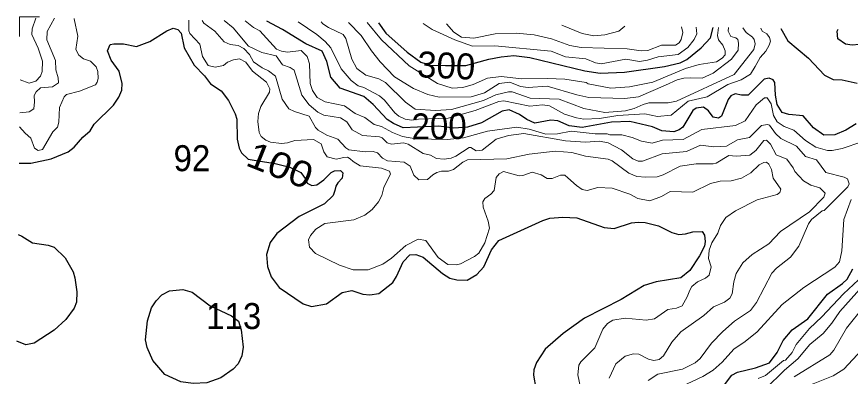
# Model space of a CAD drawing. Extents: x 673.6 to 698.9, y 7012 to 7040.1.
# Drawn here: x 674.012 to 676.578, y 7038.944 to 7040.051 of the extents above; entities that cross this region are included whole.
import ezdxf
from ezdxf.enums import TextEntityAlignment as Align

# ---------------------------------------------------------------- set-up
doc = ezdxf.new("R2010")
doc.units = 0
doc.header["$LTSCALE"] = 0.032
for name, color, linetype, lineweight in [('1', 7, 'Continuous', 25), ('2', 7, 'Continuous', 13), ('63', 7, 'Continuous', 13)]:
    doc.layers.add(name, color=color, linetype=linetype, lineweight=lineweight)
doc.layers.add('21', color=7, linetype='Continuous')
doc.layers.add('61', color=7, linetype='Continuous')

msp = doc.modelspace()

# ---------------------------------------------------------------- linework, layer by layer
at = {"layer": '1'}
for points in [[(676.5955, 7039.7209), (676.564, 7039.7015), (676.5306, 7039.6868), (676.4966, 7039.6866), (676.4646, 7039.7091), (676.4331, 7039.7461), (676.3883, 7039.7496), (676.3687, 7039.7559), (676.3527, 7039.7803), (676.3476, 7039.8095), (676.3457, 7039.8483), (676.3405, 7039.8566), (676.328, 7039.8616), (676.3123, 7039.8586), (676.2635, 7039.8091), (676.2435, 7039.8088), (676.2233, 7039.8131), (676.2097, 7039.8075), (676.2016, 7039.7956), (676.1815, 7039.7442), (676.1719, 7039.7381), (676.1563, 7039.7415), (676.1417, 7039.7608), (676.1265, 7039.7724), (676.1039, 7039.7691), (676.0937, 7039.7619), (676.0621, 7039.7103), (676.0511, 7039.7023), (676.0349, 7039.6963), (675.9982, 7039.6995), (675.9692, 7039.7121), (675.8992, 7039.7282), (675.8433, 7039.7259), (675.7527, 7039.7102), (675.7125, 7039.7152), (675.6773, 7039.73), (675.6565, 7039.7324), (675.6067, 7039.7235), (675.5825, 7039.7345), (675.5593, 7039.7502), (675.5275, 7039.7638), (675.506, 7039.7596), (675.4428, 7039.7238), (675.3992, 7039.7104), (675.3575, 7039.7082), (675.3119, 7039.7136), (675.2459, 7039.7104), (675.2018, 7039.7085), (675.1714, 7039.7218), (675.152, 7039.7347), (675.1091, 7039.7801), (675.0803, 7039.8048), (675.0073, 7039.8312), (674.9792, 7039.8644), (674.9669, 7039.9133), (674.952, 7039.9444), (674.9016, 7039.9674), (674.8305, 7040.011), (674.7819, 7040.0369)], [(675.1257, 7040.0321), (675.1487, 7039.9997), (675.214, 7039.9415), (675.2565, 7039.9106), (675.2858, 7039.9016), (675.3324, 7039.9006), (675.395, 7039.9009), (675.4652, 7039.9197), (675.5036, 7039.9275), (675.5426, 7039.9314), (675.5911, 7039.9257), (675.7605, 7039.8838), (675.8075, 7039.8772), (675.8828, 7039.8805), (676.0058, 7039.8979), (676.0542, 7039.9088), (676.0752, 7039.9189), (676.1185, 7039.9547), (676.1473, 7039.9859), (676.1559, 7040.0179)], [(674.0195, 7039.5999), (674.0552, 7039.5995), (674.1177, 7039.6135), (674.1701, 7039.6349), (674.189, 7039.649), (674.2161, 7039.6801), (674.2382, 7039.6992), (674.2507, 7039.7197), (674.3096, 7039.7781), (674.3264, 7039.8033), (674.3358, 7039.8243), (674.3366, 7039.8447), (674.3273, 7039.8834), (674.3028, 7039.917), (674.2915, 7039.9462), (674.2995, 7039.9648), (674.3112, 7039.9675), (674.341, 7039.9668), (674.3813, 7039.9595), (674.4217, 7039.9747), (674.4739, 7040.0078), (674.494, 7040.0159), (674.5084, 7040.0118), (674.5179, 7040), (674.5277, 7039.9552), (674.5583, 7039.9012), (674.5897, 7039.8689), (674.6089, 7039.844), (674.641, 7039.8227), (674.6643, 7039.7928), (674.6844, 7039.7521), (674.6892, 7039.7358), (674.691, 7039.6736), (674.6972, 7039.6463), (674.7044, 7039.6319), (674.7242, 7039.6122), (674.749, 7039.6086), (674.808, 7039.5994), (674.8532, 7039.5873), (674.8867, 7039.5711), (674.9026, 7039.5483), (674.9058, 7039.5384), (674.9205, 7039.5313), (674.9355, 7039.5332), (674.9576, 7039.5491), (674.9803, 7039.5716), (674.9904, 7039.5761), (675.0084, 7039.5779), (675.016, 7039.5701), (675.0143, 7039.5539), (675.0007, 7039.5398), (674.9944, 7039.5293), (674.9916, 7039.516), (674.9858, 7039.5), (674.9591, 7039.4745), (674.8815, 7039.4358), (674.8128, 7039.3836), (674.7919, 7039.3557), (674.781, 7039.319), (674.7838, 7039.2818), (674.7951, 7039.2497), (674.8197, 7039.2176), (674.8935, 7039.1674), (674.9193, 7039.159), (674.9656, 7039.1675), (675.0135, 7039.2023), (675.0439, 7039.2082), (675.0775, 7039.1967), (675.0988, 7039.1952), (675.1271, 7039.1987), (675.1696, 7039.2327), (675.1811, 7039.251), (675.2019, 7039.2967), (675.2222, 7039.3183), (675.241, 7039.3191), (675.2628, 7039.3109), (675.3231, 7039.2606), (675.3451, 7039.2461), (675.3667, 7039.2411), (675.3983, 7039.2398), (675.4279, 7039.2568), (675.4501, 7039.2812), (675.4739, 7039.3328), (675.4962, 7039.3618), (675.6314, 7039.4234), (675.6527, 7039.4302), (675.6933, 7039.4342), (675.7357, 7039.4318), (675.8199, 7039.4022), (675.8507, 7039.3989), (675.9042, 7039.4162), (675.9251, 7039.4186), (675.9465, 7039.4169), (675.9876, 7039.4071), (676.0284, 7039.3867)], [(676.3638, 7040.015), (676.3857, 7039.977), (676.4497, 7039.9229), (676.4985, 7039.8709), (676.5254, 7039.8574), (676.5533, 7039.8566), (676.5992, 7039.846)], [(676.6361, 7040.0112), (676.6364, 7040.0019), (676.623, 7039.9826), (676.6055, 7039.9653), (676.5835, 7039.9627), (676.5629, 7039.966), (676.5391, 7039.9825), (676.538, 7040.0059), (676.5404, 7040.0125)], [(676.0284, 7039.3867), (676.0497, 7039.3801), (676.0711, 7039.3824), (676.0929, 7039.389), (676.1216, 7039.3898), (676.1289, 7039.378)], [(674.0165, 7039.3802), (674.0274, 7039.3756), (674.061, 7039.3552), (674.1094, 7039.3478), (674.1271, 7039.3413), (674.1616, 7039.3084), (674.1855, 7039.2658), (674.1914, 7039.2469), (674.197, 7039.2037), (674.1961, 7039.1725), (674.1894, 7039.1537), (674.1631, 7039.1183), (674.1279, 7039.0855), (674.0655, 7039.0464), (674.04, 7039.0408), (674.012, 7039.0521)], [(676.1289, 7039.378), (676.1309, 7039.3593), (676.1289, 7039.3448), (676.1135, 7039.315), (676.0837, 7039.2699), (676.0558, 7039.2475), (675.9802, 7039.2344), (675.9436, 7039.2232), (675.8729, 7039.1805), (675.7599, 7039.1224), (675.694, 7039.0757), (675.639, 7039.0272), (675.6119, 7038.9867), (675.6039, 7038.9634), (675.6031, 7038.9478), (675.6096, 7038.9062)], [(676.1691, 7038.8886), (676.2131, 7038.9479), (676.2312, 7038.9569), (676.2864, 7038.9698), (676.3294, 7038.9857), (676.3528, 7039.0168), (676.3709, 7039.0546), (676.3994, 7039.0874), (676.4467, 7039.1209), (676.5081, 7039.197), (676.5534, 7039.2294), (676.5678, 7039.2431), (676.5859, 7039.2744)]]:
    msp.add_lwpolyline(points, dxfattribs=at)
msp.add_lwpolyline([(674.6943, 7039.1135), (674.7032, 7039.0867), (674.7093, 7039.0333), (674.7054, 7039.0071), (674.6933, 7038.9821), (674.6787, 7038.9662), (674.6399, 7038.9392), (674.5972, 7038.924), (674.5552, 7038.9223), (674.5176, 7038.9267), (674.4676, 7038.9493), (674.4308, 7038.9927), (674.4141, 7039.0321), (674.4082, 7039.0558), (674.4147, 7039.1142), (674.4267, 7039.1548), (674.4417, 7039.1767), (674.4584, 7039.1943), (674.4825, 7039.2067), (674.5232, 7039.2107), (674.5518, 7039.203), (674.6074, 7039.1611), (674.6735, 7039.1299)], close=True, dxfattribs=at)
at = {"layer": '2'}
for points in [[(674.1887, 7040.0451), (674.1888, 7040.0446), (674.2002, 7039.9909), (674.1939, 7039.9496), (674.203, 7039.9322), (674.2176, 7039.9208), (674.2389, 7039.9141), (674.257, 7039.8966), (674.2619, 7039.8818), (674.2627, 7039.8607), (674.26, 7039.849), (674.2544, 7039.8411), (674.2053, 7039.8221), (674.165, 7039.8114), (674.1578, 7039.8043), (674.1437, 7039.7711), (674.1419, 7039.7259), (674.138, 7039.7111), (674.1231, 7039.6963), (674.092, 7039.6417), (674.0778, 7039.6389), (674.0668, 7039.6459), (674.0559, 7039.6769), (674.0377, 7039.6922), (674.0211, 7039.712)], [(674.0217, 7039.7553), (674.0504, 7039.7578), (674.0647, 7039.7668), (674.0672, 7039.7883), (674.0656, 7039.8086), (674.0725, 7039.8199), (674.0857, 7039.8323), (674.1218, 7039.8353), (674.1403, 7039.8474), (674.1402, 7039.863), (674.1328, 7039.8874), (674.1316, 7039.9165), (674.1053, 7039.9795), (674.1058, 7040.005), (674.1281, 7040.0459)], [(674.0713, 7040.0467), (674.06, 7040.013), (674.0582, 7039.9964), (674.0777, 7039.9538), (674.0912, 7039.9143), (674.09, 7039.8818), (674.085, 7039.8679), (674.0712, 7039.8519), (674.0502, 7039.846), (674.0231, 7039.8564)], [(674.5423, 7040.0402), (674.5416, 7040.0069), (674.5449, 7039.9995), (674.5754, 7039.9665), (674.5837, 7039.9285), (674.6018, 7039.901), (674.6234, 7039.8954), (674.6487, 7039.901), (674.6611, 7039.9111), (674.6791, 7039.9184), (674.6979, 7039.9215), (674.7178, 7039.9107), (674.7377, 7039.8829), (674.7811, 7039.8498), (674.7908, 7039.8285), (674.7903, 7039.8188), (674.7639, 7039.7749), (674.7567, 7039.7526), (674.7541, 7039.7284), (674.7583, 7039.6943), (674.7643, 7039.6822), (674.7786, 7039.6704), (674.793, 7039.6644), (674.8269, 7039.6603), (674.8459, 7039.6624), (674.8683, 7039.67), (674.9254, 7039.6733), (674.9495, 7039.6595), (674.9573, 7039.6352), (674.9674, 7039.6199), (674.9949, 7039.6127), (675.0185, 7039.6174), (675.03, 7039.6184), (675.0384, 7039.6132), (675.0478, 7039.6049), (675.0688, 7039.5915), (675.1354, 7039.5845), (675.1591, 7039.5754), (675.1629, 7039.5657), (675.1568, 7039.5545), (675.1417, 7039.525), (675.1361, 7039.5005), (675.1257, 7039.4814), (675.106, 7039.4575), (675.0836, 7039.4401), (675.0497, 7039.4252), (674.961, 7039.4145), (674.9327, 7039.3967), (674.916, 7039.377), (674.9104, 7039.3644), (674.9137, 7039.3412), (674.9323, 7039.3222), (675.0052, 7039.2859), (675.048, 7039.2719), (675.0943, 7039.2716), (675.1392, 7039.2887), (675.1661, 7039.3079), (675.2096, 7039.3467), (675.2483, 7039.366), (675.2712, 7039.3617), (675.3098, 7039.3099), (675.3391, 7039.2879), (675.3645, 7039.2875), (675.3784, 7039.2904), (675.4211, 7039.3125), (675.4344, 7039.3233), (675.4528, 7039.3549), (675.4672, 7039.3999), (675.4637, 7039.4214), (675.4533, 7039.4497), (675.448, 7039.4644), (675.4471, 7039.4805), (675.4533, 7039.4916), (675.471, 7039.5045), (675.482, 7039.5163), (675.4879, 7039.5555), (675.4967, 7039.5668), (675.5105, 7039.5747), (675.5586, 7039.5608), (675.5704, 7039.5616), (675.5987, 7039.5721), (675.6269, 7039.5643), (675.645, 7039.5524), (675.6607, 7039.5524), (675.6858, 7039.5629), (675.6988, 7039.5632), (675.7089, 7039.5545), (675.7349, 7039.531), (675.7525, 7039.5194), (675.7677, 7039.5157), (675.8009, 7039.5247), (675.8446, 7039.5229), (675.8998, 7039.5044), (675.9243, 7039.4915), (675.961, 7039.4844)], [(674.6503, 7039.9737), (674.6221, 7040.0068), (674.5883, 7040.0314), (674.5831, 7040.0396)], [(674.651, 7040.0387), (674.6783, 7040.0163), (674.7251, 7039.9605), (674.7671, 7039.941), (674.8103, 7039.9307), (674.8303, 7039.903), (674.8536, 7039.8944), (674.8664, 7039.8862), (674.8902, 7039.8092), (674.9122, 7039.7799), (674.9387, 7039.7574), (674.9578, 7039.7482), (675.0085, 7039.7398), (675.0278, 7039.7276), (675.0451, 7039.7022), (675.0764, 7039.6851), (675.129, 7039.6806), (675.1367, 7039.6775), (675.1523, 7039.6629), (675.1655, 7039.6587), (675.203, 7039.6628), (675.2167, 7039.6585), (675.2634, 7039.6295), (675.2853, 7039.6249), (675.3039, 7039.6143), (675.3281, 7039.6126), (675.3495, 7039.6154), (675.3642, 7039.6216), (675.4045, 7039.6478), (675.4096, 7039.6477), (675.4265, 7039.6379), (675.4451, 7039.6398), (675.4875, 7039.6734), (675.5261, 7039.6849), (675.5732, 7039.6915), (675.701, 7039.6685), (675.7633, 7039.6651), (675.8055, 7039.6676), (675.8331, 7039.6626), (675.8736, 7039.6408), (675.9081, 7039.6129), (675.9248, 7039.6061), (675.9379, 7039.6063), (675.9985, 7039.6284), (676.0741, 7039.6354), (676.1166, 7039.6552), (676.1574, 7039.6504), (676.1965, 7039.6518), (676.2306, 7039.6723), (676.2677, 7039.6785), (676.3048, 7039.7159), (676.3228, 7039.7192), (676.3296, 7039.7165), (676.3476, 7039.6915), (676.3639, 7039.6755), (676.4123, 7039.6527), (676.4397, 7039.6209), (676.474, 7039.6101), (676.5031, 7039.5714), (676.5595, 7039.5574), (676.5695, 7039.5513), (676.5742, 7039.5361), (676.5702, 7039.5271), (676.4976, 7039.4548), (676.4913, 7039.4537), (676.4589, 7039.4271), (676.4493, 7039.4134), (676.4194, 7039.344), (676.3936, 7039.3102), (676.3505, 7039.2769), (676.3362, 7039.2614), (676.2896, 7039.1715), (676.2706, 7039.1469), (676.2212, 7039.1133), (676.1854, 7039.0823), (676.1511, 7039.0455), (676.1154, 7038.9985), (676.1007, 7038.9852), (676.061, 7038.9661), (675.9852, 7038.9507), (675.9553, 7038.931)], [(676.6134, 7039.6652), (676.5526, 7039.6454), (676.5217, 7039.6389), (676.5073, 7039.6389), (676.4723, 7039.6496), (676.4402, 7039.67), (676.4045, 7039.7019), (676.3744, 7039.7124), (676.3524, 7039.7275), (676.3411, 7039.747), (676.3339, 7039.7829), (676.3224, 7039.8015), (676.3137, 7039.8013), (676.2884, 7039.7794), (676.2543, 7039.7298), (676.2249, 7039.7164), (676.1208, 7039.7037), (676.0637, 7039.6726), (675.9994, 7039.6708), (675.9683, 7039.6619), (675.9353, 7039.6676), (675.9064, 7039.6793), (675.8742, 7039.6873), (675.8374, 7039.6874), (675.8294, 7039.6906), (675.7925, 7039.6907), (675.719, 7039.6986), (675.6768, 7039.6907), (675.6411, 7039.689), (675.5895, 7039.7047), (675.5511, 7039.7103), (675.4617, 7039.6988), (675.3874, 7039.6783), (675.3372, 7039.6731), (675.2405, 7039.6752), (675.1995, 7039.6817), (675.1688, 7039.6941), (675.1353, 7039.7127), (675.112, 7039.7191), (675.0838, 7039.7409), (675.0535, 7039.7526), (675.0213, 7039.7768), (674.9611, 7039.789), (674.9368, 7039.8025), (674.9227, 7039.8241), (674.9153, 7039.8447), (674.9134, 7039.9053), (674.9066, 7039.9287), (674.8873, 7039.9471), (674.8459, 7039.9421), (674.827, 7039.9446), (674.8113, 7039.9511), (674.7601, 7040.0076), (674.7412, 7040.0179), (674.7148, 7040.0378)], [(674.8789, 7040.0355), (674.936, 7039.9961), (674.9615, 7039.9747), (674.9786, 7039.9549), (675.0111, 7039.8902), (675.0416, 7039.8544), (675.0633, 7039.8382), (675.0807, 7039.8327), (675.1286, 7039.8077), (675.1444, 7039.7941), (675.1763, 7039.755), (675.1887, 7039.7445), (675.2083, 7039.7351), (675.228, 7039.7326), (675.2486, 7039.7358), (675.3399, 7039.7387), (675.4237, 7039.7626), (675.4965, 7039.7893), (675.5119, 7039.7917), (675.5915, 7039.7753), (675.6301, 7039.7793), (675.652, 7039.7769), (675.6986, 7039.7505), (675.7349, 7039.7391), (675.758, 7039.7359), (675.8062, 7039.7375), (675.8622, 7039.7466), (675.9454, 7039.7523), (675.9843, 7039.7441), (676.0263, 7039.7479), (676.079, 7039.7913), (676.1378, 7039.8043), (676.2006, 7039.8423), (676.2422, 7039.857), (676.2703, 7039.8739), (676.2848, 7039.8979), (676.3001, 7039.9254), (676.3181, 7039.9452), (676.3287, 7039.9633), (676.3323, 7039.9757), (676.3292, 7039.9863), (676.3208, 7039.9977), (676.3069, 7040.006), (676.3021, 7040.0158)], [(676.2467, 7040.0166), (676.2577, 7040.0023), (676.2774, 7039.9881), (676.2817, 7039.9809), (676.2851, 7039.9673), (676.2815, 7039.9498), (676.2203, 7039.8729), (676.0433, 7039.7909), (676.0175, 7039.786), (675.9582, 7039.786), (675.9404, 7039.7808), (675.913, 7039.7685), (675.8862, 7039.761), (675.8221, 7039.7556), (675.7582, 7039.7685), (675.6822, 7039.7973), (675.5926, 7039.7998), (675.5372, 7039.8192), (675.5254, 7039.8196), (675.487, 7039.8099), (675.449, 7039.7929), (675.3499, 7039.7655), (675.3011, 7039.7622), (675.2384, 7039.7667), (675.2088, 7039.7882), (675.1477, 7039.8483), (675.1272, 7039.8598), (675.0866, 7039.8708), (675.0592, 7039.8914), (675.0436, 7039.9196), (675.0253, 7039.9841), (675.0166, 7039.9958), (674.9718, 7040.0175), (674.9546, 7040.0291), (674.949, 7040.0346)], [(675.0333, 7040.0334), (675.0728, 7039.9934), (675.1039, 7039.9456), (675.1305, 7039.9117), (675.1751, 7039.8662), (675.2332, 7039.8295), (675.278, 7039.8109), (675.3124, 7039.8033), (675.4112, 7039.8042), (675.4518, 7039.8164), (675.4971, 7039.8451), (675.5304, 7039.8493), (675.5623, 7039.8364), (675.5859, 7039.8329), (675.6445, 7039.8367), (675.7359, 7039.8102), (675.7736, 7039.8024), (675.8839, 7039.799), (675.9255, 7039.8041), (676.0096, 7039.8405), (676.0452, 7039.8562), (676.0651, 7039.8615), (676.0871, 7039.8625), (676.1218, 7039.8616), (676.1557, 7039.877), (676.2121, 7039.9203), (676.2324, 7039.9474), (676.2341, 7039.9692), (676.2317, 7039.9809), (676.2254, 7039.9861), (676.2107, 7039.9903), (676.2019, 7040.0058), (676.2027, 7040.0172)], [(676.1723, 7040.0177), (676.1693, 7039.9932), (676.1725, 7039.9798), (676.1858, 7039.9631), (676.1931, 7039.9454), (676.1927, 7039.9336), (676.1835, 7039.9233), (676.1663, 7039.9124), (676.1126, 7039.9034), (676.0711, 7039.8918), (675.97, 7039.8498), (675.8979, 7039.8353), (675.8413, 7039.8312), (675.771, 7039.8443), (675.7654, 7039.8484), (675.6997, 7039.8583), (675.6457, 7039.8607), (675.5672, 7039.8591), (675.5037, 7039.8672), (675.4617, 7039.8615), (675.4166, 7039.8424), (675.3848, 7039.8329), (675.3529, 7039.8312), (675.3075, 7039.845), (675.2203, 7039.8999), (675.1352, 7039.9801), (675.0904, 7040.0326)], [(675.2635, 7040.0302), (675.2907, 7040.0119), (675.3611, 7039.9792), (675.4153, 7039.9602), (675.4837, 7039.9609), (675.6575, 7039.9452), (675.7017, 7039.9272), (675.7638, 7039.9208), (675.7933, 7039.9091), (675.8113, 7039.9059), (675.8873, 7039.9199), (675.9287, 7039.9134), (675.9534, 7039.9166), (675.987, 7039.9271), (676.0486, 7039.934), (676.0782, 7039.9555), (676.0976, 7039.9807), (676.1059, 7039.9983), (676.1034, 7040.0186)], [(676.0587, 7040.0193), (676.0622, 7040.0025), (676.0572, 7039.9802), (676.0508, 7039.9708), (676.0398, 7039.9635), (675.9972, 7039.9633), (675.9544, 7039.947), (675.9345, 7039.9462), (675.8913, 7039.9519), (675.7495, 7039.9565), (675.7145, 7039.9622), (675.6586, 7039.9824), (675.6046, 7039.9946), (675.5492, 7040.0004), (675.4844, 7039.9979), (675.4193, 7039.9849), (675.3816, 7039.9878), (675.3573, 7040.0037), (675.3347, 7040.0292)], [(675.6903, 7040.0243), (675.7522, 7039.9996), (675.7884, 7039.9923), (675.8219, 7039.9947), (675.8657, 7040.0061), (675.8838, 7040.0217)], [(674.7411, 7039.9116), (674.7287, 7039.9345), (674.7109, 7039.9525), (674.6937, 7039.9617), (674.6692, 7039.9651), (674.6503, 7039.9737)], [(675.8353, 7038.9387), (675.8561, 7038.982), (675.8848, 7039.0063), (675.9104, 7039.0134), (675.9268, 7039.012), (675.9566, 7038.997), (675.9728, 7038.993), (675.9892, 7038.9955), (676.0026, 7039.0066), (676.0286, 7039.0488), (676.0563, 7039.0805), (676.1272, 7039.1311), (676.1572, 7039.1575), (676.191, 7039.172), (676.2075, 7039.1849), (676.2145, 7039.1979), (676.2194, 7039.2344), (676.2265, 7039.2608), (676.2472, 7039.2927), (676.2754, 7039.3184), (676.3269, 7039.3513), (676.3626, 7039.3892), (676.4527, 7039.4505), (676.4966, 7039.4952), (676.5004, 7039.5072), (676.4842, 7039.5236), (676.4566, 7039.5325), (676.4341, 7039.5457), (676.4069, 7039.5748), (676.4025, 7039.5853), (676.3822, 7039.6123), (676.3502, 7039.6255), (676.3321, 7039.6584), (676.3203, 7039.6707), (676.3114, 7039.6699), (676.287, 7039.6392), (676.2682, 7039.6249), (676.2266, 7039.6216), (676.2038, 7039.6232), (676.1651, 7039.6003), (676.1556, 7039.5978), (676.1036, 7039.5977), (676.0544, 7039.5906), (676.0024, 7039.564), (675.9832, 7039.5582), (675.9487, 7039.5567), (675.9205, 7039.5592), (675.8967, 7039.5693), (675.8454, 7039.6067), (675.8325, 7039.6119), (675.7626, 7039.6218), (675.7204, 7039.6329), (675.67, 7039.6373), (675.5898, 7039.6281), (675.5208, 7039.6134), (675.3999, 7039.6102), (675.3848, 7039.6028), (675.3564, 7039.5806), (675.3414, 7039.5756), (675.3192, 7039.5754), (675.3055, 7039.5713), (675.293, 7039.5639), (675.2769, 7039.5492), (675.2496, 7039.5486), (675.2342, 7039.5633), (675.2234, 7039.591), (675.2046, 7039.6033), (675.1538, 7039.607), (675.1381, 7039.6157), (675.1222, 7039.632), (675.1096, 7039.6362), (675.0846, 7039.6348), (675.0342, 7039.6407), (675.025, 7039.6467), (675.0001, 7039.674), (674.9669, 7039.6864), (674.9396, 7039.7016), (674.9316, 7039.7097), (674.9124, 7039.7451), (674.8674, 7039.7586), (674.8502, 7039.7672), (674.8296, 7039.7971), (674.8083, 7039.8678), (674.7875, 7039.8847), (674.7676, 7039.8931), (674.7411, 7039.9116)], [(676.177, 7039.5444), (676.2115, 7039.5452), (676.2433, 7039.554), (676.2722, 7039.5701), (676.2976, 7039.5948), (676.3118, 7039.6025), (676.3199, 7039.6026), (676.3268, 7039.5972), (676.335, 7039.5801), (676.3401, 7039.5538), (676.364, 7039.52), (676.3611, 7039.5096), (676.3529, 7039.5031), (676.2913, 7039.4867), (676.2241, 7039.4536), (676.1947, 7039.4324), (676.1779, 7039.4079), (676.1701, 7039.3845), (676.1517, 7039.3547), (676.1434, 7039.3327), (676.1413, 7039.3067), (676.1495, 7039.2806), (676.1434, 7039.2552), (676.1322, 7039.2461), (676.1074, 7039.2343), (676.0906, 7039.2199), (676.084, 7039.2088), (676.0763, 7039.1881), (676.0602, 7039.1611), (676.0429, 7039.1534), (676.0159, 7039.15), (675.9756, 7039.1207), (675.9501, 7039.1163), (675.8854, 7039.1227), (675.8466, 7039.1163), (675.831, 7039.1065), (675.8166, 7039.0894), (675.7912, 7039.0317), (675.7482, 7038.9886), (675.7426, 7038.9784), (675.7395, 7038.9487), (675.7476, 7038.9095)], [(675.961, 7039.4844), (675.9967, 7039.4972), (676.0233, 7039.5129), (676.0932, 7039.5112), (676.1473, 7039.5378), (676.177, 7039.5444)], [(675.9038, 7038.4614), (675.9038, 7038.4947), (675.9284, 7038.5463), (675.9309, 7038.6267), (675.9412, 7038.6505), (675.9532, 7038.6662), (675.9678, 7038.6943), (675.9796, 7038.7783), (676.0015, 7038.8446), (676.03, 7038.894), (676.0425, 7038.9054), (676.1235, 7038.9433), (676.1554, 7038.9627), (676.1834, 7038.9874), (676.2196, 7039.0277), (676.2547, 7039.0511), (676.2916, 7039.0808), (676.3678, 7039.1652), (676.4349, 7039.2174), (676.5299, 7039.2798), (676.5444, 7039.2961), (676.5523, 7039.33), (676.5579, 7039.4265), (676.581, 7039.4883)], [(676.6034, 7039.2405), (676.5573, 7039.1978), (676.4908, 7039.1272), (676.4522, 7039.091), (676.4108, 7039.0417), (676.3991, 7039.0174), (676.3789, 7038.994), (676.3728, 7038.9927), (676.3167, 7038.9463), (676.2942, 7038.9369)], [(676.317, 7038.9057), (676.3757, 7038.9628), (676.4168, 7038.9973), (676.453, 7039.0417), (676.4949, 7039.0754), (676.5215, 7039.1077), (676.5452, 7039.1431), (676.6333, 7039.2408)], [(676.6208, 7039.1596), (676.566, 7039.0921), (676.527, 7039.0249), (676.5151, 7039.0105), (676.4053, 7038.9425)], [(676.2123, 7038.7607), (676.2304, 7038.7797), (676.2408, 7038.7822), (676.2808, 7038.804), (676.3034, 7038.8264), (676.3342, 7038.8498), (676.3965, 7038.8753), (676.4633, 7038.9206), (676.525, 7038.9454), (676.5585, 7038.9663), (676.6134, 7039.0256)]]:
    msp.add_lwpolyline(points, dxfattribs=at)
at = {"layer": '63'}
msp.add_lwpolyline([(674.0818, 7040.0509), (674.0202, 7040.0509), (674.0202, 7039.9902)], dxfattribs=at)

# ---------------------------------------------------------------- texts
at = {"layer": '21', "width": 0.95}
for s, p in [('92', (674.4949, 7039.5753)), ('113', (674.5953, 7039.0894))]:
    msp.add_text(s, height=0.08, dxfattribs=at).set_placement(p)
at = {"layer": '61'}
msp.add_text('300', height=0.08, rotation=357.36, dxfattribs=at).set_placement((675.3325, 7039.8606), align=Align.CENTER)
for s, rotation, width, p in [('200', 0.58, 0.95, (675.3127, 7039.6736)), ('100', 338.07, 1.15, (674.808, 7039.5563))]:
    msp.add_text(s, height=0.08, rotation=rotation, dxfattribs=dict(at, width=width)).set_placement(p, align=Align.CENTER)

doc.saveas('drawing.dxf')
